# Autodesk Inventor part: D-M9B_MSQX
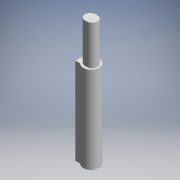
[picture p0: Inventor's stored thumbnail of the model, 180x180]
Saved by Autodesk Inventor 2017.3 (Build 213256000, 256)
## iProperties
Part Number: D-M9B_MSQX
Material: Generic
Catalog Web Link: www.cadenas.de
Description: MSQX SW-Low-Speed Rotary Table Rack & Pinion Style
Vendor: SMC
Document SubType Name: Modeling
Designer: partserver
Manufacturer: SMC
Mass: 0.394414 g
Surface Area: 4.48271 cm^2
Volume: 0.394414 cm^3
Density: 1 g/cm^3
Appearance: PSOLRGB-255-255-255
Category: PARTsolutions
Company: SMC
Title: D-M9B
Author: Cadenas PARTsolutions
Comments: Low-Speed Rotary Table Rack & Pinion Style
PSOL_IDENT_0: {$CADENAS_DATA\23d-libs\smc_jp\actuator\rotary_actuator\msqx\parts\msqx_sw.prj},163 {VTYP=3D},{NB=D-
PSOL_IDENT_1: M9B_MSQX},{LINA=D-M9B},{NN=MSQX SW},{DATE=09.12.2020 02:49:36},{GEOMDATE=19.01.2011 00:00:00},{VERSI
PSOL_IDENT_2: ON=},{LINEID=110},{WBVAR=AUTOSW},{WBNUMERIC=}  {NB=D-M9B_MSQX},{LINA=D-M9B},{KT=DUMMY},{AUTOSW=-M9B}
NB: D-M9B_MSQX
NN: MSQX SW
NT: Low-Speed Rotary Table Rack & Pinion Style
NBSYN: D$AUTOSW._MSQX
LINA: D-M9B
CATALOG: SMC (JP
AUTOSW: M9B Solid state-General-Grommet-Indicator light:Yes-2 wire-In line
SUPPLIER: SMC
ARTICLENO: D-M9B_MSQX
BOMINFO: D-M9B
CREATOR: CADENAS GmbH
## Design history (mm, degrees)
sketch "Sketch_1"
  geometry: L1 (1.428, -1.4)-(2.6, -1.4); L2 (2.6, -1.4)-(2.6, 1.4); L3 (2.6, 1.4)-(1.428, 1.4); A1 r 2 centre (0, 0) between (1.428, 1.4) and (1.428, -1.4)
  constraints: 6 end point, 2 point on circle, 1 centre point
extrude "Extrusion1" join sketch "Sketch_1" distance "d0" = 22; taper "d1" = 0 deg
sketch "Sketch_2"
  geometry: L1 (-0.25, -1.35)-(0.25, -1.35); L2 (0.25, 1.35)-(-0.25, 1.35); A1 r 1.35 centre (-0.25, 0) between (-0.25, 1.35) and (-0.25, -1.35); A2 r 1.35 centre (0.25, 0) between (0.25, -1.35) and (0.25, 1.35)
  constraints: 4 end point, 4 point on circle, 2 centre point
extrude "Extrusion2" join sketch "Sketch_2" distance "d2" = 10; taper "d3" = 0 deg
sketch "Sketch_8"
  geometry: C1 r 1.25 at (2, 0); C2 r 1.05 at (2, 0); 2 further points
  constraints: 2 centre point
extrude "Extrusion3" cut sketch "Sketch_8" distance "d4" = 0.1; taper "d5" = 0 deg
sketch "Sketch_9"
  geometry: L1 (7, 0.4)-(7, -0.4); L2 (7.4, -0.8)-(9.6, -0.8); L3 (10, -0.4)-(10, 0.4); L4 (9.6, 0.8)-(7.4, 0.8); A1 r 0.4 centre (7.4, -0.4) between (7, -0.4) and (7.4, -0.8); A2 r 0.4 centre (9.6, -0.4) between (9.6, -0.8) and (10, -0.4); A3 r 0.4 centre (9.6, 0.4) between (10, 0.4) and (9.6, 0.8); A4 r 0.4 centre (7.4, 0.4) between (7.4, 0.8) and (7, 0.4)
  constraints: 8 end point, 8 point on circle, 4 centre point
extrude "Extrusion4" cut sketch "Sketch_9" distance "d6" = 0.1; taper "d7" = 0 deg
sketch "Sketch_10"
  geometry: L1 (0.966, 0.609)-(2.609, -1.034); L2 (3.034, -0.609)-(1.391, 1.034); A1 r 1.2 centre (2, 0) between (2.609, -1.034) and (3.034, -0.609); A2 r 1.2 centre (2, 0) between (1.391, 1.034) and (0.966, 0.609)
  constraints: 4 end point, 4 point on circle, 2 centre point
extrude "Extrusion5" cut sketch "Sketch_10" distance "d8" = 0.1; taper "d9" = 0 deg
node "sw_set_XY"
node "sw_set_YZ"
node "sw_set_ZX"
node "sw_set_X"
node "sw_set_Y"
node "sw_set_Z"
node "sw_set_Center"
body "Solid1"
other parameters: "d10" = 0
